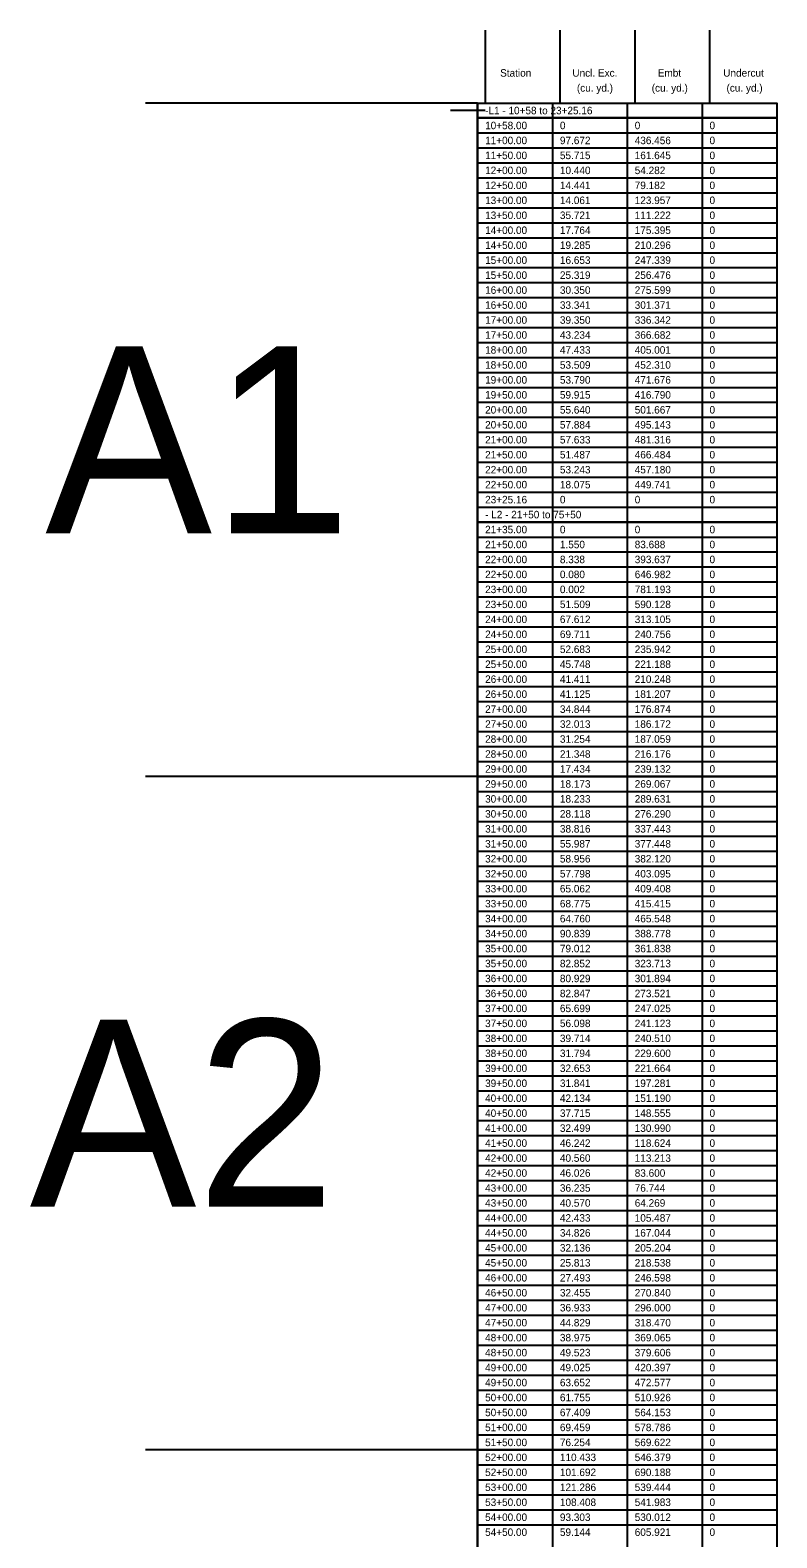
# Model space of a CAD drawing. Extents: x -124 to 80, y -10800 to 19.
# Drawn here: x -119.6 to 80, y -383.5 to 19.5 of the extents above; entities that cross this region are included whole.
import ezdxf

# ---------------------------------------------------------------- set-up
doc = ezdxf.new("R2010")
doc.units = 0
for name, color, linetype in [('Prop Shade Light', 7, 'Continuous'), ('Prop XSC Text', 7, 'Continuous'), ('Scratch_Level_1', 7, 'Continuous'), ('Scratch_Level_2', 7, 'Continuous'), ('Scratch_Level_3', 7, 'Continuous'), ('Sheet Clip Boundary CELL', 7, 'Continuous')]:
    doc.layers.add(name, color=color, linetype=linetype)

msp = doc.modelspace()

# ---------------------------------------------------------------- linework, layer by layer
at = {"layer": 'Prop Shade Light'}
for points in [[(0, 0), (80, 0), (80, -4), (0, -4)], [(0, -108), (80, -108), (80, -112), (0, -112)]]:
    msp.add_lwpolyline(points, close=True, dxfattribs=at)
at = {"layer": 'Scratch_Level_1'}
for p, q in [((2, 19.48), (2, 0)), ((22, 19.48), (22, 0)), ((42, 19.48), (42, 0)), ((62, 19.48), (62, 0)), ((0, 0), (-88.81, 0)), ((0, 0), (0, -6480)), ((0, 0), (80, 0)), ((20, 0), (20, -6480)), ((40, 0), (40, -6480)), ((60, 0), (60, -6480)), ((80, 0), (80, -6480)), ((0, -4), (80, -4)), ((0, -8), (80, -8)), ((0, -12), (80, -12)), ((0, -16), (80, -16)), ((0, -20), (80, -20)), ((0, -24), (80, -24)), ((0, -28), (80, -28)), ((0, -32), (80, -32)), ((0, -36), (80, -36)), ((0, -40), (80, -40)), ((0, -44), (80, -44)), ((0, -48), (80, -48)), ((0, -52), (80, -52)), ((0, -56), (80, -56)), ((0, -60), (80, -60)), ((0, -64), (80, -64)), ((0, -68), (80, -68)), ((0, -72), (80, -72)), ((0, -76), (80, -76)), ((0, -80), (80, -80)), ((0, -84), (80, -84)), ((0, -88), (80, -88)), ((0, -92), (80, -92)), ((0, -96), (80, -96)), ((0, -100), (80, -100)), ((0, -104), (80, -104)), ((0, -108), (80, -108)), ((0, -112), (80, -112)), ((0, -116), (80, -116)), ((0, -120), (80, -120)), ((0, -124), (80, -124)), ((0, -128), (80, -128)), ((0, -132), (80, -132)), ((0, -136), (80, -136)), ((0, -140), (80, -140)), ((0, -144), (80, -144)), ((0, -148), (80, -148)), ((0, -152), (80, -152)), ((0, -156), (80, -156)), ((0, -160), (80, -160)), ((0, -164), (80, -164)), ((0, -168), (80, -168)), ((0, -172), (80, -172)), ((0, -176), (80, -176)), ((0, -180), (-88.81, -180)), ((0, -180), (80, -180)), ((0, -184), (80, -184)), ((0, -188), (80, -188)), ((0, -192), (80, -192)), ((0, -196), (80, -196)), ((0, -200), (80, -200)), ((0, -204), (80, -204)), ((0, -208), (80, -208)), ((0, -212), (80, -212)), ((0, -216), (80, -216)), ((0, -220), (80, -220)), ((0, -224), (80, -224)), ((0, -228), (80, -228)), ((0, -232), (80, -232)), ((0, -236), (80, -236)), ((0, -240), (80, -240)), ((0, -244), (80, -244)), ((0, -248), (80, -248)), ((0, -252), (80, -252)), ((0, -256), (80, -256)), ((0, -260), (80, -260)), ((0, -264), (80, -264)), ((0, -268), (80, -268)), ((0, -272), (80, -272)), ((0, -276), (80, -276)), ((0, -280), (80, -280)), ((0, -284), (80, -284)), ((0, -288), (80, -288)), ((0, -292), (80, -292)), ((0, -296), (80, -296)), ((0, -300), (80, -300)), ((0, -304), (80, -304)), ((0, -308), (80, -308)), ((0, -312), (80, -312)), ((0, -316), (80, -316)), ((0, -320), (80, -320)), ((0, -324), (80, -324)), ((0, -328), (80, -328)), ((0, -332), (80, -332)), ((0, -336), (80, -336)), ((0, -340), (80, -340)), ((0, -344), (80, -344)), ((0, -348), (80, -348)), ((0, -352), (80, -352)), ((0, -356), (80, -356)), ((0, -360), (-88.81, -360)), ((0, -360), (80, -360)), ((0, -364), (80, -364)), ((0, -368), (80, -368)), ((0, -372), (80, -372)), ((0, -376), (80, -376)), ((0, -380), (80, -380))]:
    msp.add_line(p, q, dxfattribs=at)
at = {"layer": 'Scratch_Level_2'}
msp.add_line((2, -2), (-7.27, -2), dxfattribs=at)
at = {"layer": 'Sheet Clip Boundary CELL'}
for points in [[(0, 0), (80, 0), (80, -180), (0, -180)], [(0, -180), (80, -180), (80, -360), (0, -360)], [(0, -360), (80, -360), (80, -540), (0, -540)]]:
    msp.add_lwpolyline(points, close=True, dxfattribs=at)

# ---------------------------------------------------------------- texts
at = {"layer": 'Prop XSC Text'}
for s, p in [('Station', (6.02, 7.05)), ('Uncl. Exc.', (25.33, 7.05)), ('Embt', (48.16, 7.05)), ('Undercut', (65.67, 7.05)), ('(cu. yd.)', (26.54, 3.05)), ('(cu. yd.)', (46.54, 3.05)), ('(cu. yd.)', (66.54, 3.05)), ('-L1 - 10+58 to 23+25.16', (2, -3)), ('10+58.00', (2, -7)), ('0', (22, -7)), ('0', (42, -7)), ('0', (62, -7)), ('11+00.00', (2, -11)), ('97.672', (22, -11)), ('436.456', (42, -11)), ('0', (62, -11)), ('11+50.00', (2, -15)), ('55.715', (22, -15)), ('161.645', (42, -15)), ('0', (62, -15)), ('12+00.00', (2, -19)), ('10.440', (22, -19)), ('54.282', (42, -19)), ('0', (62, -19)), ('12+50.00', (2, -23)), ('14.441', (22, -23)), ('79.182', (42, -23)), ('0', (62, -23)), ('13+00.00', (2, -27)), ('14.061', (22, -27)), ('123.957', (42, -27)), ('0', (62, -27)), ('13+50.00', (2, -31)), ('35.721', (22, -31)), ('111.222', (42, -31)), ('0', (62, -31)), ('14+00.00', (2, -35)), ('17.764', (22, -35)), ('175.395', (42, -35)), ('0', (62, -35)), ('14+50.00', (2, -39)), ('19.285', (22, -39)), ('210.296', (42, -39)), ('0', (62, -39)), ('15+00.00', (2, -43)), ('16.653', (22, -43)), ('247.339', (42, -43)), ('0', (62, -43)), ('15+50.00', (2, -47)), ('25.319', (22, -47)), ('256.476', (42, -47)), ('0', (62, -47)), ('16+00.00', (2, -51)), ('30.350', (22, -51)), ('275.599', (42, -51)), ('0', (62, -51)), ('16+50.00', (2, -55)), ('33.341', (22, -55)), ('301.371', (42, -55)), ('0', (62, -55)), ('17+00.00', (2, -59)), ('39.350', (22, -59)), ('336.342', (42, -59)), ('0', (62, -59)), ('17+50.00', (2, -63)), ('43.234', (22, -63)), ('366.682', (42, -63)), ('0', (62, -63)), ('18+00.00', (2, -67)), ('47.433', (22, -67)), ('405.001', (42, -67)), ('0', (62, -67)), ('18+50.00', (2, -71)), ('53.509', (22, -71)), ('452.310', (42, -71)), ('0', (62, -71)), ('19+00.00', (2, -75)), ('53.790', (22, -75)), ('471.676', (42, -75)), ('0', (62, -75)), ('19+50.00', (2, -79)), ('59.915', (22, -79)), ('416.790', (42, -79)), ('0', (62, -79)), ('20+00.00', (2, -83)), ('55.640', (22, -83)), ('501.667', (42, -83)), ('0', (62, -83)), ('20+50.00', (2, -87)), ('57.884', (22, -87)), ('495.143', (42, -87)), ('0', (62, -87)), ('21+00.00', (2, -91)), ('57.633', (22, -91)), ('481.316', (42, -91)), ('0', (62, -91)), ('21+50.00', (2, -95)), ('51.487', (22, -95)), ('466.484', (42, -95)), ('0', (62, -95)), ('22+00.00', (2, -99)), ('53.243', (22, -99)), ('457.180', (42, -99)), ('0', (62, -99)), ('22+50.00', (2, -103)), ('18.075', (22, -103)), ('449.741', (42, -103)), ('0', (62, -103)), ('23+25.16', (2, -107)), ('0', (22, -107)), ('0', (42, -107)), ('0', (62, -107)), ('- L2 - 21+50 to 75+50', (2, -111)), ('21+35.00', (2, -115)), ('0', (22, -115)), ('0', (42, -115)), ('0', (62, -115)), ('21+50.00', (2, -119)), ('1.550', (22, -119)), ('83.688', (42, -119)), ('0', (62, -119)), ('22+00.00', (2, -123)), ('8.338', (22, -123)), ('393.637', (42, -123)), ('0', (62, -123)), ('22+50.00', (2, -127)), ('0.080', (22, -127)), ('646.982', (42, -127)), ('0', (62, -127)), ('23+00.00', (2, -131)), ('23+50.00', (2, -135)), ('0.002', (22, -131)), ('51.509', (22, -135)), ('590.128', (42, -135)), ('781.193', (42, -131)), ('0', (62, -131)), ('0', (62, -135)), ('24+00.00', (2, -139)), ('67.612', (22, -139)), ('313.105', (42, -139)), ('0', (62, -139)), ('24+50.00', (2, -143)), ('69.711', (22, -143)), ('240.756', (42, -143)), ('0', (62, -143)), ('25+00.00', (2, -147)), ('52.683', (22, -147)), ('235.942', (42, -147)), ('0', (62, -147)), ('25+50.00', (2, -151)), ('45.748', (22, -151)), ('221.188', (42, -151)), ('0', (62, -151)), ('26+00.00', (2, -155)), ('41.411', (22, -155)), ('210.248', (42, -155)), ('0', (62, -155)), ('26+50.00', (2, -159)), ('41.125', (22, -159)), ('181.207', (42, -159)), ('0', (62, -159)), ('27+00.00', (2, -163)), ('34.844', (22, -163)), ('176.874', (42, -163)), ('0', (62, -163)), ('27+50.00', (2, -167)), ('32.013', (22, -167)), ('186.172', (42, -167)), ('0', (62, -167)), ('28+00.00', (2, -171)), ('31.254', (22, -171)), ('187.059', (42, -171)), ('0', (62, -171)), ('28+50.00', (2, -175)), ('21.348', (22, -175)), ('216.176', (42, -175)), ('0', (62, -175)), ('29+00.00', (2, -179)), ('17.434', (22, -179)), ('239.132', (42, -179)), ('0', (62, -179)), ('29+50.00', (2, -183)), ('18.173', (22, -183)), ('269.067', (42, -183)), ('0', (62, -183)), ('30+00.00', (2, -187)), ('18.233', (22, -187)), ('289.631', (42, -187)), ('0', (62, -187)), ('30+50.00', (2, -191)), ('28.118', (22, -191)), ('276.290', (42, -191)), ('0', (62, -191)), ('31+00.00', (2, -195)), ('38.816', (22, -195)), ('337.443', (42, -195)), ('0', (62, -195)), ('31+50.00', (2, -199)), ('55.987', (22, -199)), ('377.448', (42, -199)), ('0', (62, -199)), ('32+00.00', (2, -203)), ('58.956', (22, -203)), ('382.120', (42, -203)), ('0', (62, -203)), ('32+50.00', (2, -207)), ('57.798', (22, -207)), ('403.095', (42, -207)), ('0', (62, -207)), ('33+00.00', (2, -211)), ('65.062', (22, -211)), ('409.408', (42, -211)), ('0', (62, -211)), ('33+50.00', (2, -215)), ('68.775', (22, -215)), ('415.415', (42, -215)), ('0', (62, -215)), ('34+00.00', (2, -219)), ('64.760', (22, -219)), ('465.548', (42, -219)), ('0', (62, -219)), ('34+50.00', (2, -223)), ('90.839', (22, -223)), ('388.778', (42, -223)), ('0', (62, -223)), ('35+00.00', (2, -227)), ('79.012', (22, -227)), ('361.838', (42, -227)), ('0', (62, -227)), ('35+50.00', (2, -231)), ('82.852', (22, -231)), ('323.713', (42, -231)), ('0', (62, -231)), ('36+00.00', (2, -235)), ('80.929', (22, -235)), ('301.894', (42, -235)), ('0', (62, -235)), ('36+50.00', (2, -239)), ('82.847', (22, -239)), ('273.521', (42, -239)), ('0', (62, -239)), ('37+00.00', (2, -243)), ('65.699', (22, -243)), ('247.025', (42, -243)), ('0', (62, -243)), ('37+50.00', (2, -247)), ('56.098', (22, -247)), ('241.123', (42, -247)), ('0', (62, -247)), ('38+00.00', (2, -251)), ('39.714', (22, -251)), ('240.510', (42, -251)), ('0', (62, -251)), ('38+50.00', (2, -255)), ('31.794', (22, -255)), ('229.600', (42, -255)), ('0', (62, -255)), ('39+00.00', (2, -259)), ('32.653', (22, -259)), ('221.664', (42, -259)), ('0', (62, -259)), ('39+50.00', (2, -263)), ('31.841', (22, -263)), ('197.281', (42, -263)), ('0', (62, -263)), ('40+00.00', (2, -267)), ('42.134', (22, -267)), ('151.190', (42, -267)), ('0', (62, -267)), ('40+50.00', (2, -271)), ('37.715', (22, -271)), ('148.555', (42, -271)), ('0', (62, -271)), ('41+00.00', (2, -275)), ('32.499', (22, -275)), ('130.990', (42, -275)), ('0', (62, -275)), ('41+50.00', (2, -279)), ('46.242', (22, -279)), ('118.624', (42, -279)), ('0', (62, -279)), ('42+00.00', (2, -283)), ('40.560', (22, -283)), ('113.213', (42, -283)), ('0', (62, -283)), ('42+50.00', (2, -287)), ('46.026', (22, -287)), ('83.600', (42, -287)), ('0', (62, -287)), ('43+00.00', (2, -291)), ('36.235', (22, -291)), ('76.744', (42, -291)), ('0', (62, -291)), ('43+50.00', (2, -295)), ('40.570', (22, -295)), ('64.269', (42, -295)), ('0', (62, -295)), ('44+00.00', (2, -299)), ('42.433', (22, -299)), ('105.487', (42, -299)), ('0', (62, -299)), ('44+50.00', (2, -303)), ('34.826', (22, -303)), ('167.044', (42, -303)), ('0', (62, -303)), ('45+00.00', (2, -307)), ('32.136', (22, -307)), ('205.204', (42, -307)), ('0', (62, -307)), ('45+50.00', (2, -311)), ('25.813', (22, -311)), ('218.538', (42, -311)), ('0', (62, -311)), ('46+00.00', (2, -315)), ('27.493', (22, -315)), ('246.598', (42, -315)), ('0', (62, -315)), ('46+50.00', (2, -319)), ('32.455', (22, -319)), ('270.840', (42, -319)), ('0', (62, -319)), ('47+00.00', (2, -323)), ('36.933', (22, -323)), ('296.000', (42, -323)), ('0', (62, -323)), ('47+50.00', (2, -327)), ('44.829', (22, -327)), ('318.470', (42, -327)), ('0', (62, -327)), ('48+00.00', (2, -331)), ('38.975', (22, -331)), ('369.065', (42, -331)), ('0', (62, -331)), ('48+50.00', (2, -335)), ('49.523', (22, -335)), ('379.606', (42, -335)), ('0', (62, -335)), ('49+00.00', (2, -339)), ('49.025', (22, -339)), ('420.397', (42, -339)), ('0', (62, -339)), ('49+50.00', (2, -343)), ('63.652', (22, -343)), ('472.577', (42, -343)), ('0', (62, -343)), ('50+00.00', (2, -347)), ('61.755', (22, -347)), ('510.926', (42, -347)), ('0', (62, -347)), ('50+50.00', (2, -351)), ('67.409', (22, -351)), ('564.153', (42, -351)), ('0', (62, -351)), ('51+00.00', (2, -355)), ('69.459', (22, -355)), ('578.786', (42, -355)), ('0', (62, -355)), ('51+50.00', (2, -359)), ('76.254', (22, -359)), ('569.622', (42, -359)), ('0', (62, -359)), ('52+00.00', (2, -363)), ('110.433', (22, -363)), ('546.379', (42, -363)), ('0', (62, -363)), ('52+50.00', (2, -367)), ('101.692', (22, -367)), ('690.188', (42, -367)), ('0', (62, -367)), ('53+00.00', (2, -371)), ('121.286', (22, -371)), ('539.444', (42, -371)), ('0', (62, -371)), ('53+50.00', (2, -375)), ('108.408', (22, -375)), ('541.983', (42, -375)), ('0', (62, -375)), ('54+00.00', (2, -379)), ('93.303', (22, -379)), ('530.012', (42, -379)), ('0', (62, -379)), ('54+50.00', (2, -383)), ('59.144', (22, -383)), ('605.921', (42, -383)), ('0', (62, -383))]:
    msp.add_text(s, height=2, dxfattribs=at).set_placement(p)
at = {"layer": 'Scratch_Level_3'}
for s, p in [('A1', (-115.6, -115)), ('A2', (-119.77, -295))]:
    msp.add_text(s, height=50, dxfattribs=at).set_placement(p)

doc.saveas('drawing.dxf')
